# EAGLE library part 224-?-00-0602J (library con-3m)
Zero Insertion Force Socked Source: http://www.3M.com/ehpd
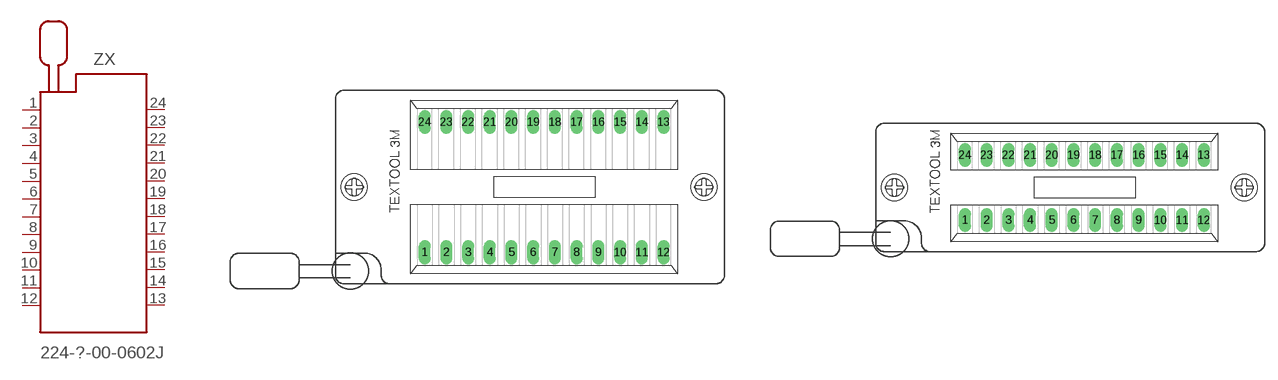
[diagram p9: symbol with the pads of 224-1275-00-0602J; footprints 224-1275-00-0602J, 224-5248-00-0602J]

Designator prefix ZX

## 224-1275-00-0602J (MF: 3M; MPN: 224-1275-00-0602J; OC_FARNELL: 9897348; OC_NEWARK: 10C2549)  [224-1275-00-0602J]
1  1  pas
2  2  pas
3  3  pas
4  4  pas
5  5  pas
6  6  pas
7  7  pas
8  8  pas
9  9  pas
10  10  pas
11  11  pas
12  12  pas
13  13  pas
14  14  pas
15  15  pas
16  16  pas
17  17  pas
18  18  pas
19  19  pas
20  20  pas
21  21  pas
22  22  pas
23  23  pas
24  24  pas

## 224-5248-00-0602J (MF: 3M; MPN: 224-5248-00-0602J; OC_FARNELL: unknown; OC_NEWARK: 85K7820)  [224-5248-00-0602J]
Pads as for 224-1275-00-0602J

## Footprint 224-1275-00-0602J (pad centres in mm)
3M TEXTOOL 24 pol. DIP Lever actuated zero insertion force mechanism Hersteller: 3M TEXTOOL Herstellerbez.: 224-1275-00-0602J Farnell Best.-Nr.: 4665454 Source: http://www.3M.com/ehpd
drill 0.9 long: 1 -13.97,-7.62; 2 -11.43,-7.62; 3 -8.89,-7.62; 4 -6.35,-7.62; 5 -3.81,-7.62; 6 -1.27,-7.62; 7 1.27,-7.62; 8 3.81,-7.62; 9 6.35,-7.62; 10 8.89,-7.62; 11 11.43,-7.62; 12 13.97,-7.62; 13 13.97,7.62; 14 11.43,7.62; 15 8.89,7.62; 16 6.35,7.62; 17 3.81,7.62; 18 1.27,7.62; 19 -1.27,7.62; 20 -3.81,7.62; 21 -6.35,7.62; 22 -8.89,7.62; 23 -11.43,7.62; 24 -13.97,7.62
hole 2 at 18.7,0
hole 2 at -22.2,0

## Footprint 224-5248-00-0602J (pad centres in mm)
3M TEXTOOL 24 pol. DIP Lever actuated zero insertion force mechanism Hersteller: 3M TEXTOOL Herstellerbez.: 224-5248-00-0602J Source: http://www.3M.com/ehpd
drill 0.9 long: 1 -13.97,-3.81; 2 -11.43,-3.81; 3 -8.89,-3.81; 4 -6.35,-3.81; 5 -3.81,-3.81; 6 -1.27,-3.81; 7 1.27,-3.81; 8 3.81,-3.81; 9 6.35,-3.81; 10 8.89,-3.81; 11 11.43,-3.81; 12 13.97,-3.81; 13 13.97,3.81; 14 11.43,3.81; 15 8.89,3.81; 16 6.35,3.81; 17 3.81,3.81; 18 1.27,3.81; 19 -1.27,3.81; 20 -3.81,3.81; 21 -6.35,3.81; 22 -8.89,3.81; 23 -11.43,3.81; 24 -13.97,3.81
hole 2 at 18.7,0
hole 2 at -22.2,0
